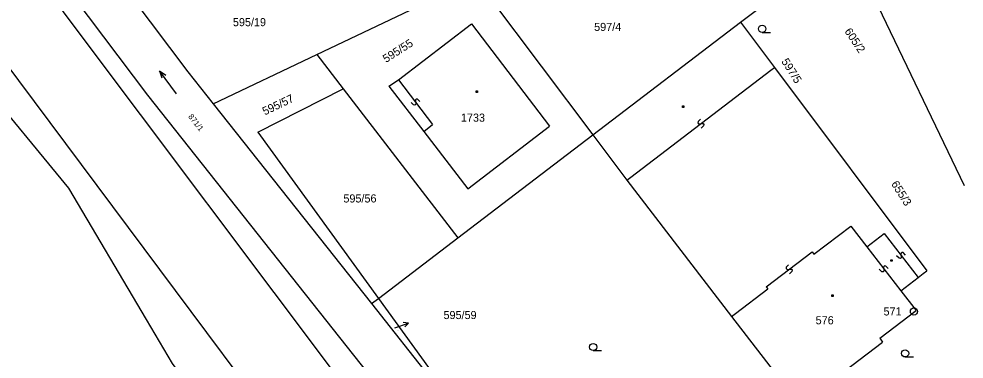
# Model space of a CAD drawing. Extents: x -493648 to -493033, y -1127718 to -1127026.
# Drawn here: x -493132.1 to -493032.8, y -1127439.8 to -1127404.1 of the extents above; entities that cross this region are included whole.
import ezdxf

# ---------------------------------------------------------------- set-up
doc = ezdxf.new("R2010")
doc.units = 0
doc.layers.add('katastrální mapa', color=7, linetype='Continuous')

msp = doc.modelspace()

# ---------------------------------------------------------------- linework, layer by layer
at = {"layer": 'katastrální mapa'}
for p, q in [((-493173.25, -1127342.08), (-493126.36, -1127404.86)), ((-493160.5, -1127356.56), (-493118.62, -1127412.12)), ((-493125.99, -1127394.24), (-493114.4, -1127409.66)), ((-493045.01, -1127396.13), (-493032.81, -1127421.58)), ((-493100.83, -1127407.84), (-493084.15, -1127399.89)), ((-493083.85, -1127400.29), (-493071.84, -1127416.28)), ((-493056.32, -1127404.44), (-493053.22, -1127402.08)), ((-493126.36, -1127404.86), (-493079.37, -1127467.4)), ((-493092.25, -1127410.48), (-493084.59, -1127404.6)), ((-493084.59, -1127404.6), (-493076.39, -1127415.35)), ((-493071.84, -1127416.28), (-493056.32, -1127404.44)), ((-493056.32, -1127404.44), (-493052.75, -1127409.2)), ((-493054.03, -1127405.51), (-493053.15, -1127405.51)), ((-493111.72, -1127413.03), (-493100.83, -1127407.84)), ((-493100.83, -1127407.84), (-493098.07, -1127411.44)), ((-493115.58, -1127411.97), (-493117.36, -1127409.55)), ((-493117.36, -1127409.55), (-493117.11, -1127410.3)), ((-493117.36, -1127409.55), (-493116.71, -1127410.01)), ((-493114.4, -1127409.66), (-493111.72, -1127413.03)), ((-493067.83, -1127420.71), (-493053.11, -1127409.48)), ((-493053.11, -1127409.48), (-493052.75, -1127409.2)), ((-493052.75, -1127409.2), (-493036.74, -1127430.56)), ((-493093.25, -1127411.16), (-493092.25, -1127410.48)), ((-493092.25, -1127410.48), (-493088.66, -1127415.17)), ((-493107.03, -1127415.99), (-493098.07, -1127411.44)), ((-493098.07, -1127411.44), (-493086.03, -1127427.11)), ((-493093.25, -1127411.16), (-493089.59, -1127415.92)), ((-493084.09, -1127411.66), (-493083.94, -1127411.66)), ((-493084.09, -1127411.81), (-493084.09, -1127411.66)), ((-493083.94, -1127411.81), (-493084.09, -1127411.81)), ((-493083.94, -1127411.66), (-493083.94, -1127411.81)), ((-493118.62, -1127412.12), (-493083.09, -1127456.9)), ((-493090.67, -1127413.12), (-493090.92, -1127412.87)), ((-493090.46, -1127412.58), (-493090.48, -1127412.72)), ((-493090.48, -1127412.72), (-493090.43, -1127412.93)), ((-493090.38, -1127412.51), (-493090.46, -1127412.58)), ((-493090.24, -1127412.53), (-493090.38, -1127412.51)), ((-493089.99, -1127412.78), (-493090.24, -1127412.53)), ((-493111.72, -1127413.03), (-493095.08, -1127434.01)), ((-493090.53, -1127413.14), (-493090.67, -1127413.12)), ((-493090.45, -1127413.07), (-493090.53, -1127413.14)), ((-493090.43, -1127412.93), (-493090.45, -1127413.07)), ((-493062.42, -1127413.24), (-493062.27, -1127413.24)), ((-493062.42, -1127413.39), (-493062.42, -1127413.24)), ((-493062.27, -1127413.39), (-493062.42, -1127413.39)), ((-493062.27, -1127413.24), (-493062.27, -1127413.39)), ((-493060.76, -1127414.88), (-493060.78, -1127415.02)), ((-493060.51, -1127414.63), (-493060.76, -1127414.88)), ((-493089.59, -1127415.92), (-493088.66, -1127415.17)), ((-493084.95, -1127421.94), (-493076.39, -1127415.35)), ((-493060.78, -1127415.02), (-493060.72, -1127415.1)), ((-493060.72, -1127415.1), (-493060.58, -1127415.12)), ((-493060.58, -1127415.12), (-493060.36, -1127415.07)), ((-493060.18, -1127415.31), (-493060.43, -1127415.56)), ((-493060.36, -1127415.07), (-493060.22, -1127415.09)), ((-493060.22, -1127415.09), (-493060.16, -1127415.17)), ((-493060.16, -1127415.17), (-493060.18, -1127415.31)), ((-493107.03, -1127415.99), (-493094.36, -1127433.46)), ((-493089.59, -1127415.92), (-493084.95, -1127421.94)), ((-493086.03, -1127427.11), (-493071.84, -1127416.28)), ((-493071.84, -1127416.28), (-493068.26, -1127421.04)), ((-493068.26, -1127421.04), (-493067.83, -1127420.71)), ((-493068.26, -1127421.04), (-493057.26, -1127435.36)), ((-493048.61, -1127428.81), (-493044.73, -1127425.87)), ((-493044.73, -1127425.87), (-493043.04, -1127428.04)), ((-493043.04, -1127428.04), (-493041.22, -1127426.63)), ((-493041.22, -1127426.63), (-493037.64, -1127431.26)), ((-493094.36, -1127433.46), (-493086.03, -1127427.11)), ((-493053.62, -1127432.23), (-493048.79, -1127428.57)), ((-493048.79, -1127428.57), (-493048.61, -1127428.81)), ((-493043.04, -1127428.04), (-493039.46, -1127432.67)), ((-493039.43, -1127428.7), (-493039.45, -1127428.84)), ((-493039.35, -1127428.63), (-493039.43, -1127428.7)), ((-493039.21, -1127428.65), (-493039.35, -1127428.63)), ((-493038.96, -1127428.9), (-493039.21, -1127428.65)), ((-493040.51, -1127429.41), (-493040.36, -1127429.41)), ((-493040.51, -1127429.56), (-493040.51, -1127429.41)), ((-493040.36, -1127429.56), (-493040.51, -1127429.56)), ((-493040.36, -1127429.41), (-493040.36, -1127429.56)), ((-493039.65, -1127429.24), (-493039.9, -1127428.99)), ((-493039.51, -1127429.26), (-493039.65, -1127429.24)), ((-493039.43, -1127429.19), (-493039.51, -1127429.26)), ((-493039.45, -1127428.84), (-493039.41, -1127429.05)), ((-493039.41, -1127429.05), (-493039.43, -1127429.19)), ((-493051.5, -1127430.18), (-493051.52, -1127430.32)), ((-493051.52, -1127430.32), (-493051.45, -1127430.4)), ((-493051.25, -1127429.93), (-493051.5, -1127430.18)), ((-493051.45, -1127430.4), (-493051.31, -1127430.42)), ((-493051.31, -1127430.42), (-493051.1, -1127430.38)), ((-493050.91, -1127430.62), (-493051.16, -1127430.87)), ((-493051.1, -1127430.38), (-493050.96, -1127430.4)), ((-493050.96, -1127430.4), (-493050.89, -1127430.48)), ((-493050.89, -1127430.48), (-493050.91, -1127430.62)), ((-493041.47, -1127430.65), (-493041.72, -1127430.4)), ((-493041.33, -1127430.67), (-493041.47, -1127430.65)), ((-493041.25, -1127430.6), (-493041.33, -1127430.67)), ((-493041.25, -1127430.11), (-493041.27, -1127430.25)), ((-493041.27, -1127430.25), (-493041.23, -1127430.46)), ((-493041.17, -1127430.04), (-493041.25, -1127430.11)), ((-493041.23, -1127430.46), (-493041.25, -1127430.6)), ((-493041.03, -1127430.06), (-493041.17, -1127430.04)), ((-493040.78, -1127430.31), (-493041.03, -1127430.06)), ((-493037.1, -1127430.83), (-493036.74, -1127430.56)), ((-493039.46, -1127432.67), (-493037.64, -1127431.26)), ((-493037.64, -1127431.26), (-493037.1, -1127430.83)), ((-493056.83, -1127435.03), (-493053.44, -1127432.47)), ((-493053.62, -1127432.23), (-493053.44, -1127432.47)), ((-493039.46, -1127432.67), (-493037.86, -1127434.74)), ((-493095.08, -1127434.01), (-493094.36, -1127433.46)), ((-493094.36, -1127433.46), (-493082.05, -1127450.44)), ((-493046.71, -1127433.1), (-493046.56, -1127433.1)), ((-493046.71, -1127433.25), (-493046.71, -1127433.1)), ((-493046.56, -1127433.25), (-493046.71, -1127433.25)), ((-493046.56, -1127433.1), (-493046.56, -1127433.25)), ((-493095.08, -1127434.01), (-493082.05, -1127450.44)), ((-493041.68, -1127437.64), (-493037.86, -1127434.74)), ((-493057.26, -1127435.36), (-493056.83, -1127435.03)), ((-493057.26, -1127435.36), (-493050.37, -1127444.23)), ((-493092.63, -1127436.54), (-493091.21, -1127436.07)), ((-493091.21, -1127436.07), (-493091.76, -1127435.99)), ((-493091.21, -1127436.07), (-493091.6, -1127436.46)), ((-493041.68, -1127437.64), (-493041.37, -1127438.06)), ((-493046.21, -1127441.73), (-493041.37, -1127438.06)), ((-493071.79, -1127438.94), (-493070.91, -1127438.94)), ((-493039.01, -1127439.61), (-493038.13, -1127439.61))]:
    msp.add_line(p, q, dxfattribs=at)
for points in [[(-493085.93, -1127472.5), (-493135.46, -1127406.14), (-493166.74, -1127364.1)], [(-493085.93, -1127472.5), (-493087.58, -1127473.97), (-493099.04, -1127458.64), (-493107.51, -1127451.54), (-493108.83, -1127450.05), (-493116, -1127440.29), (-493118.72, -1127435.67), (-493126.88, -1127421.87), (-493146.06, -1127398.58), (-493147.9, -1127396.18), (-493164.64, -1127374.21), (-493166.11, -1127372.81), (-493167.7, -1127371.62), (-493168.62, -1127371.17), (-493170.51, -1127370.59), (-493172.5, -1127370.44), (-493174.51, -1127370.65)]]:
    msp.add_lwpolyline(points, dxfattribs=at)
for centre, radius in [((-493054.03, -1127405.135), 0.375), ((-493038.08, -1127434.83), 0.375), ((-493038.08, -1127434.83), 0.005), ((-493071.79, -1127438.565), 0.375), ((-493039.01, -1127439.235), 0.375)]:
    msp.add_circle(centre, radius, dxfattribs=at)

# ---------------------------------------------------------------- texts
for s, height, p in [('595/19', 0.849996, (-493109.65, -1127404.86)), ('597/4', 0.849996, (-493071.69, -1127405.36)), ('1733', 0.849996, (-493085.69, -1127414.89)), ('595/56', 0.849996, (-493098.04, -1127423.38)), ('595/59', 0.849996, (-493087.52, -1127435.63)), ('571', 0.849996, (-493041.28, -1127435.25)), ('576', 0.849996, (-493048.41, -1127436.18)), ('595/59', 0.049998, (-493092.45, -1127436.85))]:
    msp.add_text(s, height=height, dxfattribs=at).set_placement(p)
for s, height, rotation, p in [('605/2', 0.849996, 303.6689972, (-493045.42, -1127405.4)), ('595/55', 0.849996, 32.49, (-493093.56, -1127408.73)), ('597/5', 0.849996, 302.3459972, (-493052.05, -1127408.56)), ('595/57', 0.849996, 25.497, (-493106.3, -1127414.24)), ('871/1', 0.599994, 308.484, (-493114.39, -1127414.38)), ('655/3', 0.849996, 302.3459972, (-493040.51, -1127421.43))]:
    msp.add_text(s, height=height, rotation=rotation, dxfattribs=at).set_placement(p)

doc.saveas('drawing.dxf')
